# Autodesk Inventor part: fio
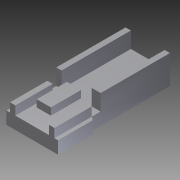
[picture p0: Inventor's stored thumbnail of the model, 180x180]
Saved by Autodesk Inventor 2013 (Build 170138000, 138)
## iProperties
Created: 2012-12
Part Number: fio
Material: Generic
Document SubType Name: Modeling
Designer: otrebor
Density: 1 g/cm^3
Author: otrebor
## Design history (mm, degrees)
sketch "Boceto1"
  geometry: L1 (0, 0)-(0, 19.566); L2 (2, 65)-(2, 21); L3 (2, 21)-(0, 19.566); L4 (2, 65)-(14.5, 65); L5 (27, 65)-(14.5, 65); L6 (27, 65)-(27, 21); L7 (27, 21)-(29, 19.566); L8 (29, 0)-(29, 19.566); L9 (0, 0)-(29, 0)
  constraints: 18 end point, 2 perpendicular, 1 parallel, 1 vertical
extrude "Extrusión1" new body sketch "Boceto1" distance "d3" = 7; taper "d4" = 0 deg
sketch "Boceto2"
  geometry: L1 (27, 65)-(27, 21) reference; L2 (2, 65)-(27, 65) reference; L3 (2, 21)-(2, 65) reference; L4 (2, 65)-(5, 65); L5 (2, 65)-(2, 26); L6 (5, 26)-(5, 65); L7 (27, 65)-(24, 65); L8 (24, 65)-(24, 44); L9 (27, 65)-(27, 26); L10 (5, 26)-(2, 26); L11 (24, 26)-(27, 26); L12 (24.123, 26)-(22, 26); L13 (22, 26)-(22, 44); L14 (22, 44)-(24, 44)
  constraints: 22 end point, 5 perpendicular, 2 collinear, 2 point on line, 1 parallel, 1 other
  dimensions: "d7" = 18 distance of L12.end L13.end
extrude "Extrusión2" join sketch "Boceto2" distance "d5" = 9; taper "d6" = 0 deg
sketch "Boceto3"
  geometry: L1 (5, 65)-(24, 65) reference; L2 (29, 0)-(0, 0) reference; L3 (22, 44)-(24, 44) reference; L4 (2, 0)-(2, 21); L5 (2, 21)-(5, 21); L6 (5, 21)-(5, 0); L7 (5, 0)-(2, 0); L8 (27, 21)-(24, 21); L9 (24, 21)-(24, 0); L10 (27, 0)-(27, 21); L11 (24, 0)-(27, 0)
  constraints: 16 end point, 4 perpendicular, 1 parallel
  dimensions: "d9" = 21 distance of L5.end L6.end
extrude "Extrusión3" join sketch "Boceto3" distance "d10" = 5; taper "d11" = 0 deg
sketch "Boceto4"
  geometry: L1 (29, 0)-(0, 0) reference; L2 (7, 10)-(15, 10); L3 (15, 10)-(15, 27); L4 (15, 27)-(7, 27); L5 (7, 27)-(7, 10) reference
  constraints: 8 end point, 2 parallel, 1 perpendicular, 1 vertical
  dimensions: "d22" = 8 distance of L2.start L2.end
extrude "Extrusión4" join sketch "Boceto4" distance "d16" = 4; taper "d17" = 0 deg
node "Sólido1"
